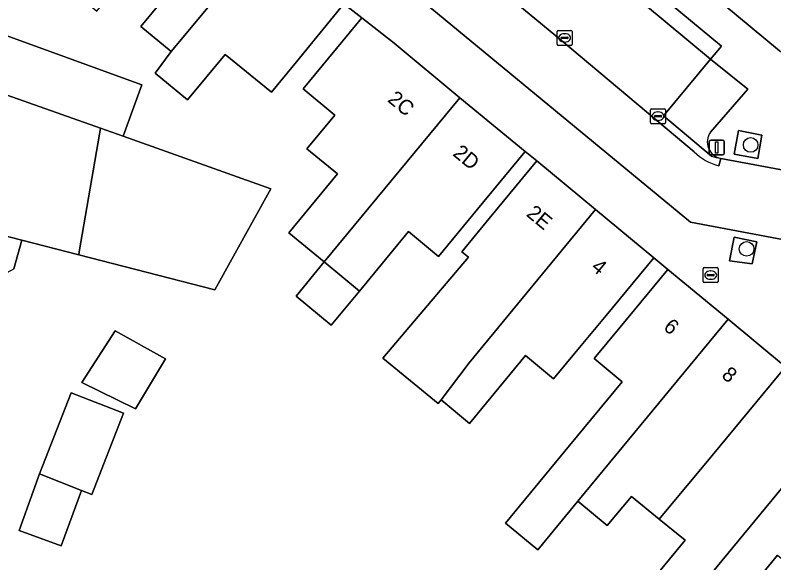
# Model space of a CAD drawing. Extents: x 160157 to 160921, y 381516 to 382045.
# Drawn here: x 160314.8 to 160365.5, y 381893.9 to 381930.5 of the extents above; entities that cross this region are included whole.
import ezdxf

# ---------------------------------------------------------------- set-up
doc = ezdxf.new("R2010")
doc.units = 0
for name, color, linetype in [('IMGEO_Boom', 7, 'Continuous'), ('IMGEO_Brandkraan', 7, 'Continuous'), ('IMGEO_Erf', 7, 'Continuous'), ('IMGEO_Groenvoorziening', 7, 'Continuous'), ('IMGEO_Haag', 7, 'Continuous'), ('IMGEO_Kolk', 7, 'Continuous'), ('IMGEO_Lichtmast', 7, 'Continuous'), ('IMGEO_Pand', 7, 'Continuous'), ('IMGEO_Pand_nummerreeks', 7, 'Continuous'), ('IMGEO_Parkeervlak_open', 7, 'Continuous'), ('IMGEO_Rijbaan_lokaal_open', 7, 'Continuous'), ('IMGEO_Verkeerseiland_groen', 7, 'Continuous'), ('IMGEO_Voetpad_open', 7, 'Continuous')]:
    doc.layers.add(name, color=color, linetype=linetype)

msp = doc.modelspace()

# ---------------------------------------------------------------- linework, layer by layer
at = {"layer": 'IMGEO_Boom'}
for centre in [(160363.935, 381921.839), (160363.664, 381914.896)]:
    msp.add_circle(centre, 0.489, dxfattribs=at)
at = {"layer": 'IMGEO_Brandkraan'}
for p, q in [((160360.762, 381912.717), (160360.762, 381913.569)), ((160360.837, 381913.643), (160361.689, 381913.643)), ((160361.25, 381913.423), (160361.275, 381913.423)), ((160361.763, 381913.569), (160361.763, 381912.717)), ((160361.021, 381913.137), (160361.021, 381913.149)), ((160361.459, 381913.1), (160361.061, 381913.1)), ((160361.064, 381913.186), (160361.462, 381913.186)), ((160361.273, 381912.863), (160361.248, 381912.863)), ((160361.505, 381913.149), (160361.505, 381913.137)), ((160361.689, 381912.643), (160360.837, 381912.643))]:
    msp.add_line(p, q, dxfattribs=at)
for points in [[(160360.762, 381912.717), (160360.762, 381913.569)], [(160360.837, 381913.643), (160361.689, 381913.643)], [(160361.763, 381913.569), (160361.763, 381912.717)], [(160361.689, 381912.643), (160360.837, 381912.643)]]:
    msp.add_lwpolyline(points, dxfattribs=at)
for centre, radius, start, end in [((160360.839, 381913.567), 0.0765, 91.552, 178.448), ((160360.839, 381913.567), 0.0765, 91.552, 178.448), ((160361.687, 381913.567), 0.0765, 1.552, 88.448), ((160361.687, 381913.567), 0.0765, 1.552, 88.448), ((160361.061, 381913.146), 0.0403, 85.8775, 175.7526), ((160361.058, 381913.136), 0.0366, 178.938, 274.7102), ((160361.462, 381913.143), 0.043, 264.8664, 352.4533), ((160361.466, 381913.148), 0.0386, 1.7309, 96.639), ((160360.839, 381912.719), 0.0765, 181.552, 268.448), ((160360.839, 381912.719), 0.0765, 181.552, 268.448), ((160361.687, 381912.719), 0.0765, 271.552, 358.448), ((160361.687, 381912.719), 0.0765, 271.552, 358.448)]:
    msp.add_arc(centre, radius, start, end, dxfattribs=at)
for centre, major_axis, ratio, start_param, end_param in [((160361.249, 381913.143), (-0.387, 0.002), 0.722429, 4.712389, 7.853982), ((160361.274, 381913.143), (-0.39, 0.002), 0.717154, 1.570796, 4.712389)]:
    msp.add_ellipse(centre, major_axis=major_axis, ratio=ratio, start_param=start_param, end_param=end_param, dxfattribs=at)
at = {"layer": 'IMGEO_Erf'}
for points in [[(160344.409, 381965.211), (160342.3, 381962.646), (160340.171, 381960.057), (160339.912, 381959.742), (160343.551, 381956.749), (160347.187, 381953.76), (160349.646, 381956.751), (160351.654, 381959.193), (160353.667, 381957.538), (160351.659, 381955.096), (160349.425, 381952.38), (160349.212, 381952.121), (160352.884, 381949.102), (160353.024, 381948.987), (160353.303, 381949.327), (160356.629, 381946.593), (160359.23, 381944.455), (160362.603, 381948.557), (160365.262, 381946.365), (160359.777, 381939.701), (160356.601, 381935.838), (160365.87, 381928.117)], [(160355.174, 381890.116), (160359.564, 381895.43), (160357.829, 381896.842), (160355.962, 381898.362), (160354.347, 381896.41), (160352.381, 381898.035), (160349.704, 381894.798), (160347.549, 381896.578), (160351.838, 381901.769), (160355.35, 381906.02), (160353.481, 381907.564), (160355.22, 381909.668), (160358.404, 381913.522), (160357.461, 381914.308), (160354.277, 381910.454), (160352.49, 381908.299), (160350.765, 381906.219), (160348.893, 381907.772), (160347.112, 381905.617), (160345.145, 381903.236), (160343.243, 381904.807), (160343.047, 381904.565), (160339.351, 381907.599), (160345.08, 381914.344), (160344.64, 381914.702), (160346.454, 381916.918), (160349.638, 381920.772), (160348.857, 381921.395), (160345.673, 381917.541), (160343.072, 381914.392), (160341.066, 381916.049), (160337.785, 381912.078), (160335.904, 381909.801), (160333.549, 381911.748), (160335.43, 381914.024), (160333.068, 381915.975), (160336.313, 381919.902), (160334.278, 381921.584), (160336.14, 381923.835), (160334.03, 381925.58), (160337.94, 381930.325), (160336.75, 381931.258), (160333.571, 381927.4), (160331.909, 381925.366), (160328.82, 381927.88), (160326.295, 381924.858), (160324.13, 381926.642), (160325.21, 381928.07), (160323.177, 381929.746), (160324.583, 381931.452)], [(160314.104, 381929.169), (160323.234, 381925.853), (160321.987, 381922.418), (160331.871, 381918.918), (160328.115, 381912.15), (160319.03, 381914.492), (160315.222, 381915.474), (160314.69, 381913.569)], [(160365.729, 381894.427), (160363.72, 381891.995)]]:
    msp.add_lwpolyline(points, dxfattribs=at)
for points in [[(160322.814, 381904.217), (160319.244, 381905.971), (160321.452, 381909.417), (160324.816, 381907.56)], [(160319.894, 381898.496), (160319.204, 381898.766), (160317.859, 381895.054), (160315.036, 381896.077), (160316.406, 381899.858), (160318.526, 381905.286), (160322.013, 381903.924)]]:
    msp.add_lwpolyline(points, close=True, dxfattribs=at)
at = {"layer": 'IMGEO_Groenvoorziening'}
msp.add_lwpolyline([(160356.044, 381933.38), (160355.318, 381932.519), (160361.259, 381927.56), (160361.986, 381928.441)], close=True, dxfattribs=at)
at = {"layer": 'IMGEO_Haag'}
msp.add_lwpolyline([(160361.259, 381927.56), (160361.986, 381928.441), (160356.044, 381933.38), (160355.318, 381932.519)], close=True, dxfattribs=at)
at = {"layer": 'IMGEO_Kolk'}
for p, q in [((160351, 381928.565), (160351, 381929.417)), ((160351.075, 381929.491), (160351.927, 381929.491)), ((160351.488, 381929.271), (160351.513, 381929.271)), ((160352.001, 381929.417), (160352.001, 381928.565)), ((160351.259, 381928.985), (160351.259, 381928.997)), ((160351.697, 381928.948), (160351.299, 381928.948)), ((160351.302, 381929.034), (160351.7, 381929.034)), ((160351.511, 381928.711), (160351.486, 381928.711)), ((160351.743, 381928.997), (160351.743, 381928.985)), ((160351.927, 381928.491), (160351.075, 381928.491)), ((160357.241, 381923.334), (160357.241, 381924.186)), ((160357.316, 381924.26), (160358.168, 381924.26)), ((160357.729, 381924.04), (160357.754, 381924.04)), ((160358.242, 381924.186), (160358.242, 381923.334)), ((160357.5, 381923.754), (160357.5, 381923.766)), ((160357.938, 381923.717), (160357.54, 381923.717)), ((160357.543, 381923.803), (160357.941, 381923.803)), ((160357.984, 381923.766), (160357.984, 381923.754)), ((160358.168, 381923.26), (160357.316, 381923.26)), ((160357.752, 381923.48), (160357.727, 381923.48))]:
    msp.add_line(p, q, dxfattribs=at)
for points in [[(160351, 381928.565), (160351, 381929.417)], [(160351.075, 381929.491), (160351.927, 381929.491)], [(160352.001, 381929.417), (160352.001, 381928.565)], [(160351.927, 381928.491), (160351.075, 381928.491)], [(160357.241, 381923.334), (160357.241, 381924.186)], [(160357.316, 381924.26), (160358.168, 381924.26)], [(160358.242, 381924.186), (160358.242, 381923.334)], [(160358.168, 381923.26), (160357.316, 381923.26)]]:
    msp.add_lwpolyline(points, dxfattribs=at)
for centre, radius, start, end in [((160351.077, 381929.415), 0.0765, 91.552, 178.448), ((160351.077, 381929.415), 0.0765, 91.552, 178.448), ((160351.925, 381929.415), 0.0765, 1.552, 88.448), ((160351.925, 381929.415), 0.0765, 1.552, 88.448), ((160351.077, 381928.567), 0.0765, 181.552, 268.448), ((160351.077, 381928.567), 0.0765, 181.552, 268.448), ((160351.299, 381928.994), 0.0403, 85.8775, 175.7526), ((160351.296, 381928.984), 0.0366, 178.938, 274.7102), ((160351.7, 381928.991), 0.043, 264.8664, 352.4533), ((160351.704, 381928.996), 0.0386, 1.7309, 96.639), ((160351.925, 381928.567), 0.0765, 271.552, 358.448), ((160351.925, 381928.567), 0.0765, 271.552, 358.448), ((160357.318, 381924.184), 0.0765, 91.552, 178.448), ((160357.318, 381924.184), 0.0765, 91.552, 178.448), ((160358.166, 381924.184), 0.0765, 1.552, 88.448), ((160358.166, 381924.184), 0.0765, 1.552, 88.448), ((160357.54, 381923.763), 0.0403, 85.8775, 175.7526), ((160357.537, 381923.753), 0.0366, 178.938, 274.7102), ((160357.941, 381923.76), 0.043, 264.8664, 352.4533), ((160357.945, 381923.765), 0.0386, 1.7309, 96.639), ((160357.318, 381923.336), 0.0765, 181.552, 268.448), ((160357.318, 381923.336), 0.0765, 181.552, 268.448), ((160358.166, 381923.336), 0.0765, 271.552, 358.448), ((160358.166, 381923.336), 0.0765, 271.552, 358.448)]:
    msp.add_arc(centre, radius, start, end, dxfattribs=at)
for centre, major_axis, ratio, start_param, end_param in [((160351.487, 381928.991), (-0.387, 0.002), 0.722429, 4.712389, 7.853982), ((160351.512, 381928.991), (-0.39, 0.002), 0.717154, 1.570796, 4.712389), ((160357.728, 381923.76), (-0.387, 0.002), 0.722429, 4.712389, 7.853982), ((160357.753, 381923.76), (-0.39, 0.002), 0.717154, 1.570796, 4.712389)]:
    msp.add_ellipse(centre, major_axis=major_axis, ratio=ratio, start_param=start_param, end_param=end_param, dxfattribs=at)
at = {"layer": 'IMGEO_Lichtmast'}
for p, q in [((160361.172, 381921.268), (160361.172, 381922.068)), ((160361.172, 381922.068), (160361.172, 381921.268)), ((160361.272, 381922.168), (160362.062, 381922.168)), ((160362.062, 381922.168), (160361.272, 381922.168)), ((160362.162, 381922.068), (160362.162, 381921.268)), ((160362.162, 381921.268), (160362.162, 381922.068)), ((160362.062, 381921.168), (160361.272, 381921.168)), ((160361.272, 381921.168), (160362.062, 381921.168))]:
    msp.add_line(p, q, dxfattribs=at)
msp.add_lwpolyline([(160361.592, 381922.043), (160361.742, 381922.043), (160361.742, 381921.293), (160361.592, 381921.293), (160361.592, 381922.043)], dxfattribs=at)
for centre, start, end in [((160361.272, 381922.068), 90, 180), ((160361.272, 381922.068), 90, 180), ((160362.062, 381922.068), 0, 90), ((160362.062, 381922.068), 360, 90), ((160361.272, 381921.268), 180, 270), ((160361.272, 381921.268), 180, 270), ((160362.062, 381921.268), 270, 0), ((160362.062, 381921.268), 270, 0)]:
    msp.add_arc(centre, 0.1, start, end, dxfattribs=at)
at = {"layer": 'IMGEO_Pand'}
for points in [[(160319.551, 381931.345), (160320.241, 381930.777), (160322.328, 381933.31), (160324.583, 381931.452), (160323.177, 381929.746), (160325.21, 381928.07), (160331.466, 381935.613), (160326.419, 381939.772)], [(160306.362, 381934.633), (160306.247, 381934.658), (160306.273, 381935.002), (160298.94, 381936.479), (160297.869, 381931.467), (160305.117, 381929.863), (160304.815, 381928.497), (160310.186, 381926.596), (160310.498, 381926.485), (160320.481, 381922.951), (160321.987, 381922.418), (160323.234, 381925.853), (160314.104, 381929.169), (160311.218, 381929.737), (160311.319, 381930.195), (160310.237, 381930.434), (160305.656, 381931.448), (160305.939, 381932.725), (160306.074, 381933.334), (160306.209, 381933.943)], [(160325.21, 381928.07), (160324.13, 381926.642), (160326.295, 381924.858), (160328.82, 381927.88), (160331.909, 381925.366), (160333.571, 381927.4), (160336.75, 381931.258), (160331.466, 381935.613)], [(160310.498, 381926.485), (160310.186, 381926.596), (160304.815, 381928.497), (160297.644, 381930.479), (160295.847, 381920.47), (160315.222, 381915.474), (160319.03, 381914.492), (160319.065, 381914.694), (160320.415, 381922.565), (160320.481, 381922.951)], [(160344.499, 381924.996), (160340.102, 381928.629), (160337.94, 381930.325), (160334.03, 381925.58), (160336.14, 381923.835), (160334.278, 381921.584), (160336.313, 381919.902), (160333.068, 381915.975), (160335.43, 381914.024)], [(160335.43, 381914.024), (160337.785, 381912.078), (160341.066, 381916.049), (160343.072, 381914.392), (160345.673, 381917.541), (160348.857, 381921.395), (160344.499, 381924.996)], [(160321.987, 381922.418), (160320.481, 381922.951), (160320.415, 381922.565), (160319.065, 381914.694), (160319.03, 381914.492), (160328.115, 381912.15), (160331.871, 381918.918)], [(160303.485, 381915.581), (160313.339, 381912.824), (160314.69, 381913.569), (160315.222, 381915.474), (160295.847, 381920.47), (160294.829, 381920.702), (160293.452, 381910.947), (160298.077, 381910.156), (160298.29, 381911.74), (160302.165, 381910.806), (160302.119, 381910.583), (160302.383, 381910.492)], [(160353.572, 381917.522), (160349.638, 381920.772), (160346.454, 381916.918), (160344.64, 381914.702), (160345.08, 381914.344), (160339.351, 381907.599), (160343.047, 381904.565), (160343.243, 381904.807), (160345.118, 381907.291)], [(160354.277, 381910.454), (160357.461, 381914.308), (160353.572, 381917.522), (160345.118, 381907.291), (160343.243, 381904.807), (160345.145, 381903.236), (160347.112, 381905.617), (160348.893, 381907.772), (160350.765, 381906.219), (160352.49, 381908.299)], [(160337.785, 381912.078), (160335.43, 381914.024), (160333.549, 381911.748), (160335.904, 381909.801)], [(160362.436, 381910.191), (160358.404, 381913.522), (160355.22, 381909.668), (160353.481, 381907.564), (160355.35, 381906.02), (160351.838, 381901.769), (160347.549, 381896.578), (160349.704, 381894.798), (160352.381, 381898.035)], [(160357.829, 381896.842), (160361.358, 381901.088), (160366.268, 381907.024), (160362.436, 381910.191), (160352.381, 381898.035), (160354.347, 381896.41), (160355.962, 381898.362)], [(160322.814, 381904.217), (160324.816, 381907.56), (160321.452, 381909.417), (160319.244, 381905.971)], [(160370.1, 381903.857), (160366.268, 381907.024), (160361.358, 381901.088), (160357.829, 381896.842), (160359.564, 381895.43), (160355.174, 381890.116), (160357.328, 381888.337), (160360.344, 381892.002), (160361.687, 381893.685)], [(160322.013, 381903.924), (160318.526, 381905.286), (160316.406, 381899.858), (160319.204, 381898.766), (160319.894, 381898.496)], [(160370.1, 381903.857), (160361.687, 381893.685), (160360.344, 381892.002), (160362.354, 381890.342), (160363.72, 381891.995), (160365.729, 381894.427), (160367.533, 381892.936), (160369.015, 381894.735), (160370.747, 381896.838), (160373.931, 381900.692)], [(160319.204, 381898.766), (160316.406, 381899.858), (160315.036, 381896.077), (160317.859, 381895.054)]]:
    msp.add_lwpolyline(points, close=True, dxfattribs=at)
at = {"layer": 'IMGEO_Parkeervlak_open'}
for points in [[(160317.74, 381957.054), (160315.541, 381958.892), (160315.245, 381958.534), (160351.289, 381928.805), (160360.149, 381921.379)], [(160361.321, 381921.094), (160358.101, 381923.793), (160361.259, 381927.56), (160355.318, 381932.519), (160354.461, 381933.234), (160348.464, 381938.24), (160345.331, 381934.336), (160342.956, 381936.295), (160342.202, 381936.917), (160345.394, 381940.788), (160337.502, 381947.343)], [(160361.815, 381920.44), (160361.944, 381920.939)]]:
    msp.add_lwpolyline(points, dxfattribs=at)
for centre, radius, start, end in [((160362.735, 381924.02), 3.696, 225.5994, 255.5871), ((160362.587, 381924.854), 3.967, 251.3878, 260.6696)]:
    msp.add_arc(centre, radius, start, end, dxfattribs=at)
at = {"layer": 'IMGEO_Rijbaan_lokaal_open'}
for points in [[(160360.149, 381921.379), (160351.289, 381928.805), (160315.245, 381958.534), (160315.541, 381958.892), (160316.098, 381959.567), (160315.4, 381960.173), (160312.536, 381962.804), (160309.064, 381958.612), (160359.924, 381916.684), (160369.605, 381914.849), (160369.748, 381915.384)], [(160424.697, 381875.722), (160372.344, 381919.004), (160361.944, 381920.939), (160361.815, 381920.44)]]:
    msp.add_lwpolyline(points, dxfattribs=at)
msp.add_arc((160362.735, 381924.02), 3.696, 225.5994, 255.5871, dxfattribs=at)
at = {"layer": 'IMGEO_Verkeerseiland_groen'}
for points in [[(160364.674, 381922.495), (160363.118, 381922.803), (160362.824, 381921.227), (160364.41, 381920.929)], [(160364.345, 381915.374), (160362.836, 381915.684), (160362.525, 381914.093), (160364.038, 381913.895)]]:
    msp.add_lwpolyline(points, close=True, dxfattribs=at)
at = {"layer": 'IMGEO_Voetpad_open'}
for points in [[(160417.865, 381885.448), (160409.913, 381891.762), (160405.98, 381895.008), (160402.178, 381898.146), (160398.377, 381901.283), (160394.442, 381904.531), (160393.686, 381905.155), (160389.982, 381908.211), (160386.102, 381911.413), (160382.063, 381914.747), (160381.302, 381915.381), (160377.373, 381918.624), (160373.586, 381921.749), (160369.799, 381924.874), (160365.87, 381928.117), (160356.601, 381935.838), (160348.017, 381942.896), (160343.315, 381946.762), (160338.557, 381950.675), (160333.919, 381954.488), (160329.267, 381958.313), (160324.402, 381962.313), (160323.63, 381962.943), (160319.596, 381966.674)], [(160312.536, 381962.804), (160315.4, 381960.173), (160320.432, 381961.41), (160321.685, 381961.718), (160328.425, 381956.194), (160327.742, 381955.36), (160329.226, 381954.16), (160329.878, 381955.035), (160337.343, 381948.854), (160336.672, 381947.995), (160337.502, 381947.343), (160338.181, 381948.144), (160346.828, 381941.024), (160346.146, 381940.163), (160348.464, 381938.24), (160349.158, 381939.008), (160355.173, 381934.108), (160354.461, 381933.234), (160355.318, 381932.519), (160356.044, 381933.38), (160361.986, 381928.441), (160361.259, 381927.56), (160363.739, 381925.575), (160361.243, 381922.685)], [(160304.159, 381960.798), (160302.654, 381953.794), (160302.402, 381952.62), (160303.648, 381952.346), (160314.547, 381949.911), (160320.573, 381944.944), (160320.396, 381944.729), (160321.073, 381944.178), (160326.419, 381939.772), (160331.466, 381935.613), (160336.75, 381931.258), (160337.94, 381930.325), (160340.102, 381928.629), (160344.499, 381924.996), (160348.857, 381921.395), (160349.638, 381920.772), (160353.572, 381917.522), (160357.461, 381914.308), (160358.404, 381913.522), (160362.436, 381910.191), (160366.268, 381907.024)], [(160369.605, 381914.849), (160359.924, 381916.684), (160309.064, 381958.612), (160308.058, 381959.424)], [(160363.739, 381925.575), (160361.259, 381927.56), (160358.101, 381923.793), (160361.321, 381921.094)], [(160361.243, 381922.685), (160363.739, 381925.575)], [(160361.944, 381920.939), (160372.344, 381919.004), (160424.697, 381875.722), (160428.691, 381866.326)]]:
    msp.add_lwpolyline(points, dxfattribs=at)
for points in [[(160364.41, 381920.929), (160362.824, 381921.227), (160363.118, 381922.803), (160364.674, 381922.495)], [(160364.038, 381913.895), (160362.525, 381914.093), (160362.836, 381915.684), (160364.345, 381915.374)]]:
    msp.add_lwpolyline(points, close=True, dxfattribs=at)
for centre, radius, start, end in [((160362.157, 381922.038), 1.12, 144.7198, 259.0301), ((160362.157, 381922.038), 1.12, 144.7198, 259.0301), ((160362.587, 381924.854), 3.967, 251.3878, 260.6696)]:
    msp.add_arc(centre, radius, start, end, dxfattribs=at)

# ---------------------------------------------------------------- texts
at = {"layer": 'IMGEO_Pand_nummerreeks'}
for s, rotation, p in [('2C', 320.4373, (160339.61, 381924.78)), ('2D', 320.4332, (160343.969, 381921.179)), ('2E', 320.4373, (160348.879, 381917.144)), ('4', 320.4258, (160353.215, 381913.562)), ('6', 320.433, (160358.043, 381909.565)), ('8', 320.433, (160361.928, 381906.355))]:
    msp.add_text(s, height=1, rotation=rotation, dxfattribs=at).set_placement(p)

doc.saveas('drawing.dxf')
